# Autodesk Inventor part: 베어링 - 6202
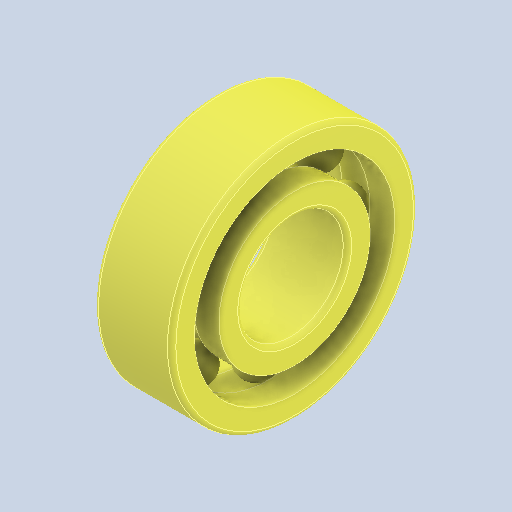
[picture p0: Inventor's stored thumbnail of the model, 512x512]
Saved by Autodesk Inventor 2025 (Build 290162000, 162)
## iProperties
Created: 2024-07
Part Number: 베어링 - 6202
Material: 강, 연강
Description: 깊은 그루브 볼 베어링
Document SubType Name: Modeling
Designer: samsung
Density: 7.86 g/cm^3
Appearance: 기본값
Author: jhkim
Sending System: Autodesk Inventor 2025
Preprocessor: ST-DEVELOPER v20
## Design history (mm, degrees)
feature "Solid1"
feature "Solid1:1"
feature "Solid1:2"
feature "Solid1:3"
feature "Solid1:4"
feature "Solid1:5"
feature "Solid1:6"
feature "Solid1:7"
feature "Solid1:8"
feature "Solid1:9"
node "솔리드1"
node "솔리드2"
node "솔리드3"
node "솔리드4"
node "솔리드5"
node "솔리드6"
node "솔리드7"
node "솔리드8"
node "솔리드9"
node "솔리드10"
